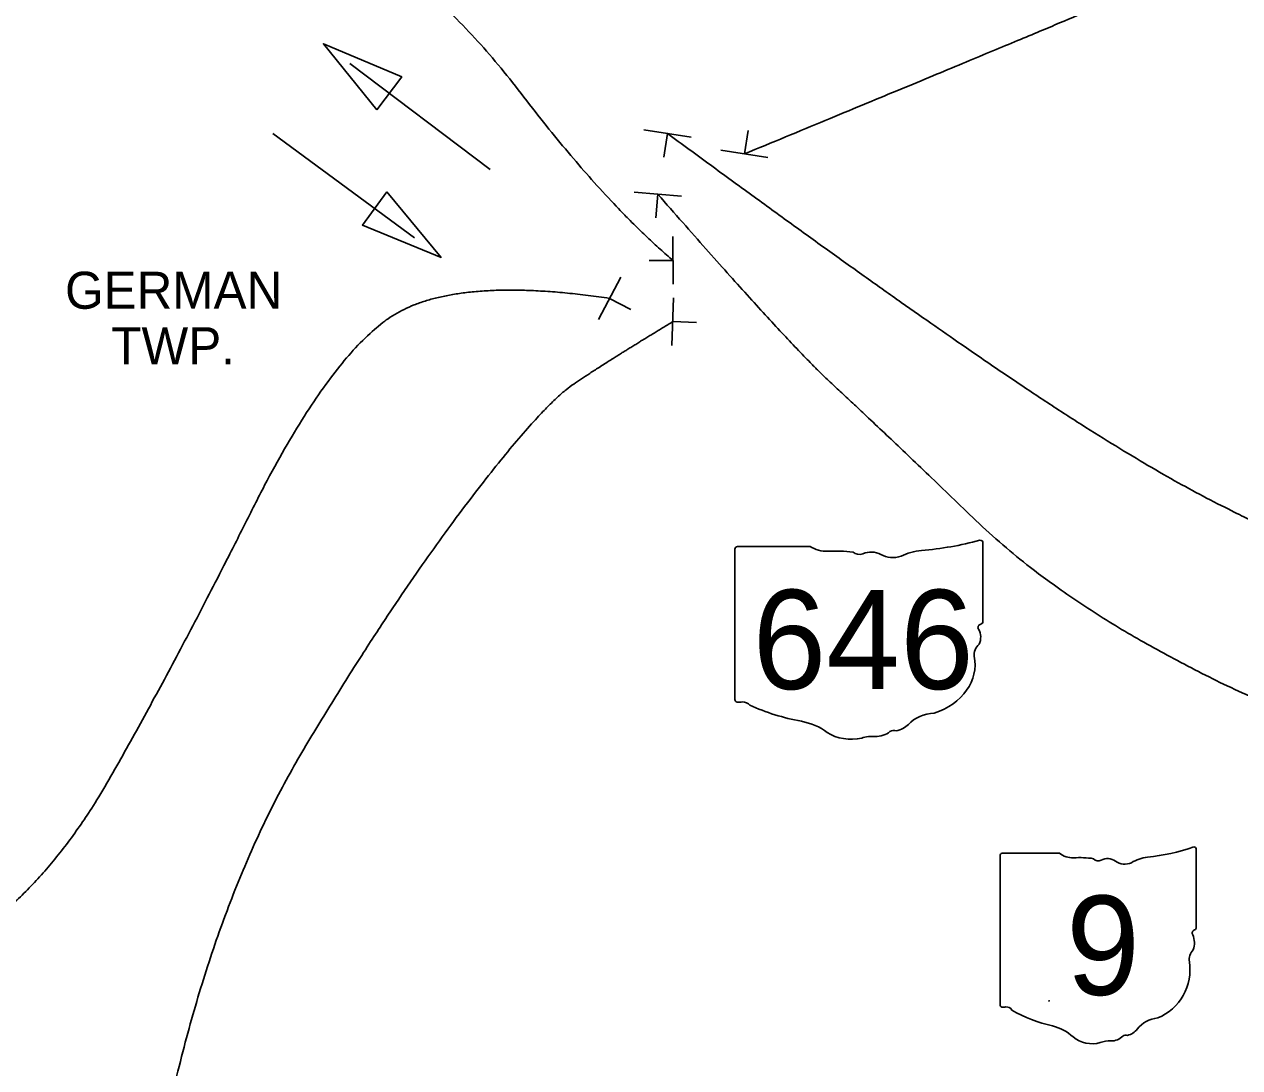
# Model space of a CAD drawing. Extents: x -740 to 1519, y 0 to 440.
# Drawn here: x 442.8 to 534.8, y 67.2 to 146.1 of the extents above; entities that cross this region are included whole.
import ezdxf

# ---------------------------------------------------------------- set-up
doc = ezdxf.new("R2010")
doc.units = 0
for name, color, linetype in [('Default', 7, 'Continuous'), ('GM_X_County_Road_Text', 7, 'Continuous'), ('GM_X_Minor_River', 7, 'Continuous'), ('GM_X_Section', 7, 'Continuous'), ('GM_X_Section_Text', 7, 'Continuous'), ('SH_Data', 7, 'Continuous')]:
    doc.layers.add(name, color=color, linetype=linetype)

msp = doc.modelspace()

# ---------------------------------------------------------------- linework, layer by layer
at = {"layer": 'Default'}
for p, q in [((467.442, 143.109), (478.068, 135.098)), ((472.342, 129.933), (461.617, 137.81))]:
    msp.add_line(p, q, dxfattribs=at)
for points in [[(469.494, 139.608), (465.45, 144.61), (471.372, 142.1)], [(470.247, 133.407), (474.352, 128.456), (468.4, 130.893)]]:
    msp.add_lwpolyline(points, close=True, dxfattribs=at)
at = {"layer": 'GM_X_County_Road_Text'}
for p, q in [((515.327, 100.919), (515.327, 106.875)), ((496.578, 106.397), (496.578, 95.012)), ((502.253, 106.593), (496.762, 106.593)), ((515.325, 100.921), (515.327, 100.919)), ((531.46, 77.795), (531.46, 83.684)), ((516.628, 83.211), (516.628, 71.955)), ((521.118, 83.405), (516.774, 83.405)), ((531.458, 77.797), (531.46, 77.795))]:
    msp.add_line(p, q, dxfattribs=at)
for centre, radius, start, end in [((526.177, 98.752), 15.728, 275.84447, 288.90645), ((531.295, 83.708), 0.165, 351.86209, 97.738), ((516.798, 83.235), 0.172, 98.1301, 188.1301), ((522.152, 84.712), 1.667, 231.61951, 271.11188), ((522.705, 77.085), 5.983, 80.48669, 94.98827), ((524.063, 83.294), 0.481, 219.79206, 297.10237), ((524.769, 81.993), 1, 54.46668, 119.14113), ((526.059, 83.777), 1.203, 233.85621, 294.82819), ((528.183, 79.967), 3.164, 97.34618, 120.76885), ((531.422, 77.363), 0.256, 107.94398, 210.33697), ((529.796, 76.619), 1.534, 340.03296, 23.64957), ((531.284, 77.773), 0.177, 289.60381, 7.73413), ((532.051, 75.331), 1.116, 136.8065, 186.92959), ((527.058, 74.582), 3.934, 292.30889, 8.98584), ((516.8, 71.93), 0.173, 171.95839, 258.30661), ((516.826, 73.082), 1.323, 267.33899, 280.60386), ((517.097, 71.305), 0.477, 29.74838, 93.27175), ((523.119, 81.419), 11.358, 240.41292, 257.1985), ((528.716, 68.794), 2.155, 94.40312, 142.57675), ((519.733, 66.897), 3.554, 47.18416, 75.83597), ((525.987, 70.864), 1.271, 282.87319, 323.27711), ((523.576, 71.249), 2.255, 230.70037, 286.29184), ((524.879, 67.357), 1.853, 85.69512, 111.20995), ((525.044, 70.406), 1.201, 268.77702, 315.54927), ((526.131, 69.316), 0.338, 65.75173, 132.64842)]:
    msp.add_arc(centre, radius, start, end, dxfattribs=at)
for centre, major_axis, start_param, end_param in [((508.648, 122.114), (19.884, 0), 4.814394, 5.042369), ((515.119, 106.9), (0.209, 0), 6.141152, 7.989035), ((496.792, 106.421), (0.217, 0), 1.712693, 3.28349), ((503.561, 107.914), (2.107, 0), 4.042523, 4.731795), ((504.259, 100.201), (7.564, 0), 1.404758, 1.657858), ((505.976, 106.48), (0.608, 0), 3.836095, 5.185415), ((506.869, 105.164), (1.264, 0), 0.950623, 2.079405), ((508.5, 106.969), (1.52, 0), 4.081561, 5.145723), ((511.185, 103.116), (4, 0), 1.699011, 2.107814), ((515.279, 100.482), (0.323, 0), 1.883978, 3.671073), ((513.224, 99.729), (1.939, 0), 5.934695, 6.695948), ((515.105, 100.896), (0.223, 0), 5.05454, 6.418171), ((516.075, 98.427), (1.411, 0), 2.387724, 3.262537), ((509.762, 97.67), (4.973, 0), 5.101752, 6.440018), ((496.794, 94.987), (0.219, 0), 3.00124, 4.508301), ((496.828, 96.152), (1.672, 0), 4.665946, 4.897461), ((497.17, 94.355), (0.603, 0), 0.519207, 1.627899), ((504.783, 104.584), (14.359, 0), 4.195997, 4.488961), ((511.859, 91.816), (2.724, 0), 1.647645, 2.488434), ((500.502, 89.898), (4.493, 0), 0.823519, 1.323587), ((508.408, 93.909), (1.607, 0), 4.937069, 5.64225), ((505.361, 94.299), (2.851, 0), 4.026481, 4.996735), ((507.008, 90.363), (2.342, 0), 1.495662, 1.94098), ((507.217, 93.446), (1.519, 0), 4.691044, 5.507374), ((508.591, 92.344), (0.428, 0), 1.147584, 2.315152)]:
    msp.add_ellipse(centre, major_axis=major_axis, ratio=0.8, start_param=start_param, end_param=end_param, dxfattribs=at)
at = {"layer": 'GM_X_Minor_River'}
for p, q in [((489.696, 138.097), (493.254, 137.548)), ((497.291, 136.276), (497.565, 138.055)), ((491.475, 137.822), (491.201, 136.043)), ((499.07, 136.002), (495.512, 136.551)), ((488.957, 133.381), (492.543, 133.072)), ((490.75, 133.227), (490.595, 131.434)), ((491.881, 130.022), (491.897, 126.422)), ((491.889, 128.222), (490.089, 128.214)), ((486.254, 123.768), (487.944, 126.946)), ((487.099, 125.357), (488.688, 124.512)), ((491.811, 121.795), (491.928, 125.393)), ((491.87, 123.594), (493.669, 123.535))]:
    msp.add_line(p, q, dxfattribs=at)
at = {"layer": 'GM_X_Section_Text'}
for p, q in [((525.68, 73.776), (525.68, 73.79)), ((525.682, 73.79), (525.682, 73.788)), ((525.682, 73.786), (525.682, 73.776)), ((525.688, 73.79), (525.688, 73.79)), ((525.69, 73.78), (525.69, 73.78)), ((520.322, 72.246), (520.314, 72.232)), ((520.329, 72.231), (520.329, 72.231)), ((520.334, 72.237), (520.336, 72.237)), ((520.337, 72.235), (520.334, 72.235)), ((520.339, 72.236), (520.339, 72.236)), ((520.344, 72.231), (520.344, 72.231))]:
    msp.add_line(p, q, dxfattribs=at)
for points in [[(520.314, 72.23), (520.323, 72.23), (520.323, 72.225)], [(520.328, 72.232), (520.325, 72.232), (520.325, 72.246)], [(520.325, 72.225), (520.325, 72.23), (520.328, 72.23)]]:
    msp.add_lwpolyline(points, dxfattribs=at)
msp.add_lwpolyline([(520.323, 72.245), (520.323, 72.232), (520.316, 72.232), (520.323, 72.245)], close=True, dxfattribs=at)
for points in [[(525.68, 73.79), (525.68, 73.791), (525.68, 73.791)], [(525.68, 73.791), (525.68, 73.791), (525.68, 73.791)], [(525.68, 73.791), (525.68, 73.791), (525.681, 73.791)], [(525.68, 73.787), (525.68, 73.788), (525.681, 73.788)], [(525.681, 73.785), (525.68, 73.786), (525.68, 73.787)], [(525.68, 73.777), (525.68, 73.778), (525.68, 73.778)], [(525.68, 73.778), (525.68, 73.778), (525.68, 73.778)], [(525.68, 73.778), (525.68, 73.778), (525.68, 73.778)], [(525.68, 73.778), (525.68, 73.778), (525.68, 73.778)], [(525.68, 73.778), (525.681, 73.778), (525.681, 73.778)], [(525.68, 73.776), (525.68, 73.776), (525.68, 73.777)], [(525.68, 73.777), (525.68, 73.777), (525.68, 73.777)], [(525.681, 73.776), (525.68, 73.776), (525.68, 73.776)], [(525.68, 73.775), (525.68, 73.776), (525.68, 73.776)], [(525.681, 73.775), (525.68, 73.775), (525.68, 73.775)], [(525.68, 73.775), (525.68, 73.775), (525.68, 73.775)], [(525.681, 73.791), (525.681, 73.791), (525.681, 73.791)], [(525.681, 73.791), (525.681, 73.791), (525.682, 73.791)], [(525.681, 73.788), (525.681, 73.789), (525.682, 73.79)], [(525.682, 73.784), (525.681, 73.785), (525.681, 73.785)], [(525.681, 73.778), (525.681, 73.778), (525.682, 73.777)], [(525.682, 73.775), (525.681, 73.776), (525.681, 73.776)], [(525.682, 73.775), (525.681, 73.775), (525.681, 73.775)], [(525.681, 73.775), (525.681, 73.775), (525.681, 73.775)], [(525.682, 73.79), (525.682, 73.79), (525.683, 73.791)], [(525.682, 73.791), (525.682, 73.791), (525.682, 73.791)], [(525.682, 73.791), (525.682, 73.791), (525.682, 73.791)], [(525.682, 73.791), (525.682, 73.791), (525.682, 73.79)], [(525.682, 73.788), (525.683, 73.789), (525.683, 73.79)], [(525.683, 73.789), (525.683, 73.788), (525.682, 73.788)], [(525.682, 73.788), (525.682, 73.788), (525.682, 73.787)], [(525.682, 73.787), (525.682, 73.786), (525.683, 73.786)], [(525.683, 73.787), (525.683, 73.787), (525.682, 73.786)], [(525.683, 73.783), (525.682, 73.784), (525.682, 73.784)], [(525.682, 73.777), (525.682, 73.777), (525.683, 73.777)], [(525.682, 73.776), (525.682, 73.776), (525.682, 73.775)], [(525.683, 73.775), (525.682, 73.775), (525.682, 73.775)], [(525.682, 73.775), (525.682, 73.775), (525.682, 73.775)], [(525.682, 73.775), (525.682, 73.775), (525.682, 73.775)], [(525.683, 73.791), (525.684, 73.791), (525.685, 73.791)], [(525.683, 73.79), (525.684, 73.79), (525.684, 73.791)], [(525.684, 73.789), (525.683, 73.789), (525.683, 73.789)], [(525.684, 73.788), (525.684, 73.788), (525.683, 73.787)], [(525.683, 73.786), (525.683, 73.785), (525.684, 73.785)], [(525.684, 73.783), (525.684, 73.783), (525.683, 73.783)], [(525.683, 73.777), (525.684, 73.777), (525.685, 73.777)], [(525.684, 73.775), (525.684, 73.775), (525.683, 73.775)], [(525.684, 73.791), (525.685, 73.791), (525.685, 73.791)], [(525.685, 73.789), (525.685, 73.789), (525.684, 73.789)], [(525.685, 73.789), (525.685, 73.789), (525.684, 73.788)], [(525.684, 73.785), (525.684, 73.785), (525.685, 73.784)], [(525.686, 73.782), (525.685, 73.782), (525.684, 73.783)], [(525.687, 73.775), (525.686, 73.775), (525.684, 73.775)], [(525.685, 73.791), (525.686, 73.791), (525.687, 73.791)], [(525.685, 73.791), (525.686, 73.791), (525.686, 73.791)], [(525.687, 73.789), (525.686, 73.789), (525.685, 73.789)], [(525.686, 73.789), (525.686, 73.789), (525.685, 73.789)], [(525.685, 73.784), (525.685, 73.784), (525.686, 73.784)], [(525.685, 73.777), (525.685, 73.777), (525.686, 73.777)], [(525.686, 73.791), (525.686, 73.791), (525.687, 73.791)], [(525.687, 73.789), (525.686, 73.789), (525.686, 73.789)], [(525.686, 73.784), (525.687, 73.783), (525.688, 73.783)], [(525.687, 73.781), (525.686, 73.782), (525.686, 73.782)], [(525.686, 73.777), (525.687, 73.777), (525.687, 73.777)], [(525.687, 73.791), (525.687, 73.791), (525.688, 73.791)], [(525.687, 73.791), (525.687, 73.791), (525.687, 73.791)], [(525.687, 73.791), (525.688, 73.791), (525.688, 73.791)], [(525.688, 73.789), (525.687, 73.789), (525.687, 73.789)], [(525.688, 73.789), (525.688, 73.789), (525.687, 73.789)], [(525.687, 73.789), (525.687, 73.789), (525.687, 73.789)], [(525.688, 73.781), (525.687, 73.781), (525.687, 73.781)], [(525.687, 73.777), (525.688, 73.778), (525.688, 73.778)], [(525.688, 73.776), (525.688, 73.776), (525.687, 73.775)], [(525.688, 73.791), (525.688, 73.791), (525.688, 73.79)], [(525.688, 73.791), (525.688, 73.791), (525.688, 73.791)], [(525.688, 73.791), (525.688, 73.791), (525.688, 73.791)], [(525.688, 73.791), (525.688, 73.79), (525.688, 73.79)], [(525.688, 73.79), (525.689, 73.79), (525.689, 73.79)], [(525.688, 73.79), (525.688, 73.789), (525.688, 73.789)], [(525.688, 73.79), (525.688, 73.79), (525.688, 73.79)], [(525.688, 73.79), (525.688, 73.79), (525.688, 73.79)], [(525.688, 73.788), (525.688, 73.789), (525.688, 73.789)], [(525.688, 73.789), (525.688, 73.789), (525.688, 73.789)], [(525.688, 73.789), (525.688, 73.789), (525.688, 73.789)], [(525.688, 73.789), (525.688, 73.789), (525.688, 73.789)], [(525.688, 73.789), (525.688, 73.789), (525.688, 73.789)], [(525.689, 73.788), (525.689, 73.788), (525.688, 73.788)], [(525.688, 73.783), (525.688, 73.783), (525.689, 73.782)], [(525.688, 73.779), (525.688, 73.78), (525.688, 73.781)], [(525.688, 73.778), (525.688, 73.779), (525.688, 73.779)], [(525.69, 73.778), (525.689, 73.777), (525.688, 73.776)], [(525.689, 73.79), (525.689, 73.79), (525.689, 73.79)], [(525.689, 73.79), (525.689, 73.79), (525.689, 73.79)], [(525.689, 73.79), (525.689, 73.79), (525.689, 73.789)], [(525.689, 73.789), (525.689, 73.789), (525.689, 73.789)], [(525.689, 73.789), (525.689, 73.789), (525.689, 73.789)], [(525.689, 73.789), (525.689, 73.789), (525.689, 73.789)], [(525.689, 73.789), (525.689, 73.788), (525.689, 73.788)], [(525.689, 73.788), (525.689, 73.788), (525.689, 73.788)], [(525.689, 73.782), (525.689, 73.782), (525.69, 73.781)], [(525.69, 73.781), (525.69, 73.781), (525.69, 73.78)], [(525.69, 73.78), (525.69, 73.779), (525.69, 73.778)], [(520.314, 72.232), (520.314, 72.232), (520.314, 72.232)], [(520.314, 72.232), (520.314, 72.232), (520.314, 72.232)], [(520.314, 72.232), (520.314, 72.232), (520.314, 72.231)], [(520.314, 72.231), (520.314, 72.231), (520.314, 72.231)], [(520.314, 72.231), (520.314, 72.231), (520.314, 72.231)], [(520.314, 72.231), (520.314, 72.231), (520.314, 72.23)], [(520.314, 72.23), (520.314, 72.23), (520.314, 72.23)], [(520.314, 72.23), (520.314, 72.23), (520.314, 72.23)], [(520.323, 72.246), (520.323, 72.246), (520.322, 72.246)], [(520.322, 72.246), (520.322, 72.246), (520.322, 72.246)], [(520.324, 72.246), (520.323, 72.246), (520.323, 72.246)], [(520.323, 72.246), (520.323, 72.246), (520.323, 72.246)], [(520.323, 72.225), (520.323, 72.225), (520.323, 72.225)], [(520.323, 72.225), (520.323, 72.225), (520.324, 72.225)], [(520.325, 72.246), (520.325, 72.246), (520.324, 72.246)], [(520.324, 72.246), (520.324, 72.246), (520.324, 72.246)], [(520.324, 72.225), (520.324, 72.225), (520.324, 72.225)], [(520.324, 72.225), (520.324, 72.225), (520.324, 72.225)], [(520.324, 72.225), (520.325, 72.225), (520.325, 72.225)], [(520.325, 72.246), (520.325, 72.246), (520.325, 72.246)], [(520.325, 72.246), (520.325, 72.246), (520.325, 72.246)], [(520.325, 72.225), (520.325, 72.225), (520.325, 72.225)], [(520.325, 72.225), (520.325, 72.225), (520.325, 72.225)], [(520.325, 72.225), (520.325, 72.225), (520.325, 72.225)], [(520.329, 72.231), (520.329, 72.232), (520.328, 72.232)], [(520.328, 72.232), (520.328, 72.232), (520.328, 72.232)], [(520.328, 72.23), (520.328, 72.23), (520.328, 72.231)], [(520.328, 72.231), (520.329, 72.231), (520.329, 72.231)], [(520.332, 72.244), (520.332, 72.245), (520.332, 72.245)], [(520.332, 72.245), (520.333, 72.245), (520.333, 72.245)], [(520.332, 72.243), (520.332, 72.244), (520.332, 72.244)], [(520.332, 72.244), (520.332, 72.244), (520.332, 72.244)], [(520.332, 72.244), (520.332, 72.244), (520.332, 72.244)], [(520.333, 72.243), (520.332, 72.243), (520.332, 72.243)], [(520.332, 72.243), (520.332, 72.243), (520.332, 72.243)], [(520.332, 72.227), (520.332, 72.227), (520.332, 72.228)], [(520.332, 72.228), (520.332, 72.228), (520.332, 72.228)], [(520.332, 72.228), (520.332, 72.228), (520.332, 72.228)], [(520.332, 72.228), (520.332, 72.228), (520.333, 72.228)], [(520.332, 72.226), (520.332, 72.226), (520.332, 72.227)], [(520.332, 72.227), (520.332, 72.227), (520.332, 72.227)], [(520.332, 72.227), (520.332, 72.227), (520.332, 72.227)], [(520.333, 72.226), (520.332, 72.226), (520.332, 72.226)], [(520.333, 72.245), (520.334, 72.246), (520.334, 72.246)], [(520.333, 72.245), (520.333, 72.245), (520.333, 72.245)], [(520.334, 72.244), (520.334, 72.244), (520.333, 72.243)], [(520.333, 72.243), (520.333, 72.243), (520.333, 72.243)], [(520.333, 72.243), (520.333, 72.243), (520.333, 72.243)], [(520.333, 72.228), (520.333, 72.228), (520.334, 72.227)], [(520.334, 72.225), (520.333, 72.226), (520.333, 72.226)], [(520.334, 72.246), (520.335, 72.246), (520.336, 72.246)], [(520.336, 72.245), (520.335, 72.244), (520.334, 72.244)], [(520.334, 72.236), (520.334, 72.237), (520.334, 72.237)], [(520.334, 72.237), (520.334, 72.237), (520.334, 72.237)], [(520.334, 72.237), (520.334, 72.237), (520.334, 72.237)], [(520.334, 72.235), (520.334, 72.235), (520.334, 72.236)], [(520.334, 72.236), (520.334, 72.236), (520.334, 72.236)], [(520.334, 72.236), (520.334, 72.236), (520.334, 72.236)], [(520.334, 72.235), (520.334, 72.235), (520.334, 72.235)], [(520.334, 72.235), (520.334, 72.235), (520.334, 72.235)], [(520.334, 72.227), (520.334, 72.227), (520.335, 72.227)], [(520.335, 72.225), (520.334, 72.225), (520.334, 72.225)], [(520.335, 72.227), (520.336, 72.227), (520.338, 72.227)], [(520.337, 72.225), (520.336, 72.225), (520.335, 72.225)], [(520.336, 72.246), (520.337, 72.247), (520.338, 72.247)], [(520.338, 72.245), (520.337, 72.245), (520.336, 72.245)], [(520.336, 72.237), (520.337, 72.237), (520.338, 72.237)], [(520.339, 72.235), (520.338, 72.235), (520.337, 72.235)], [(520.34, 72.225), (520.339, 72.225), (520.337, 72.225)], [(520.338, 72.247), (520.339, 72.247), (520.34, 72.246)], [(520.339, 72.245), (520.339, 72.245), (520.338, 72.245)], [(520.338, 72.237), (520.339, 72.238), (520.34, 72.238)], [(520.338, 72.227), (520.339, 72.227), (520.34, 72.227)], [(520.34, 72.244), (520.34, 72.244), (520.339, 72.245)], [(520.341, 72.237), (520.34, 72.236), (520.339, 72.236)], [(520.339, 72.236), (520.34, 72.236), (520.341, 72.236)], [(520.341, 72.234), (520.34, 72.235), (520.339, 72.235)], [(520.34, 72.246), (520.341, 72.246), (520.342, 72.245)], [(520.341, 72.243), (520.341, 72.243), (520.34, 72.244)], [(520.34, 72.238), (520.341, 72.239), (520.341, 72.239)], [(520.34, 72.227), (520.34, 72.227), (520.341, 72.228)], [(520.343, 72.227), (520.342, 72.226), (520.34, 72.225)], [(520.341, 72.241), (520.341, 72.242), (520.341, 72.243)], [(520.341, 72.239), (520.341, 72.24), (520.341, 72.241)], [(520.342, 72.238), (520.342, 72.237), (520.341, 72.237)], [(520.341, 72.236), (520.342, 72.235), (520.343, 72.235)], [(520.342, 72.233), (520.341, 72.233), (520.341, 72.234)], [(520.341, 72.228), (520.342, 72.228), (520.342, 72.229)], [(520.342, 72.245), (520.343, 72.244), (520.343, 72.244)], [(520.343, 72.24), (520.343, 72.239), (520.342, 72.238)], [(520.342, 72.231), (520.342, 72.232), (520.342, 72.233)], [(520.342, 72.229), (520.342, 72.23), (520.342, 72.231)], [(520.343, 72.244), (520.343, 72.243), (520.343, 72.241)], [(520.343, 72.241), (520.343, 72.24), (520.343, 72.24)], [(520.343, 72.235), (520.344, 72.234), (520.344, 72.233)], [(520.344, 72.229), (520.344, 72.227), (520.343, 72.227)], [(520.344, 72.233), (520.344, 72.232), (520.344, 72.231)], [(520.344, 72.231), (520.344, 72.23), (520.344, 72.229)]]:
    msp.add_open_spline(points, degree=2, dxfattribs=at)
at = {"layer": 'SH_Data'}
msp.add_circle((495, 118.25), 90, dxfattribs=at)
for points in [[(411.478, 171.473), (430.143, 170.678), (446.411, 165.935), (458.908, 157.743), (473.991, 149.227), (486.596, 132.734), (491.889, 128.222)], [(591.92, 157.705), (590.626, 153.517), (588.033, 149.489), (581.373, 145.107), (566.146, 145.009), (547.531, 146.268), (529.802, 149.818), (516.164, 144.084), (497.291, 136.276)], [(611.833, 101.317), (606.078, 94.563), (591.428, 94.196), (571.108, 96.351), (552.943, 101.781), (538.845, 106.805), (525.441, 113.826), (505.786, 127.29), (491.475, 137.822)], [(617.24, 73.665), (616.801, 84.587), (609.026, 86.824), (597.525, 86.07), (588.476, 86.447), (546.998, 89.843), (521.97, 101.643), (507.447, 115.641), (500.623, 121.909), (490.75, 133.227)], [(404.527, 68.644), (430.669, 72.259), (444.243, 80.183), (454.424, 98.104), (465.548, 120.364), (474.974, 127.155), (487.099, 125.357)], [(412.592, 37.021), (434.928, 41.722), (450.388, 49.268), (457.552, 80.583), (470.561, 102.277), (481.873, 117.18), (486.844, 120.545), (491.87, 123.594)]]:
    msp.add_open_spline(points, degree=2, dxfattribs=at)

# ---------------------------------------------------------------- texts
at = {"layer": 'GM_X_County_Road_Text'}
for s, p in [('646', (497.905, 95.815)), ('9', (521.627, 72.688))]:
    msp.add_text(s, height=7.5, dxfattribs=at).set_placement(p)
at = {"layer": 'GM_X_Section'}
for s, p in [('GERMAN ', (445.907, 124.569)), ('TWP.', (449.402, 120.369))]:
    msp.add_text(s, height=2.8, dxfattribs=at).set_placement(p)

doc.saveas('drawing.dxf')
